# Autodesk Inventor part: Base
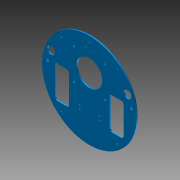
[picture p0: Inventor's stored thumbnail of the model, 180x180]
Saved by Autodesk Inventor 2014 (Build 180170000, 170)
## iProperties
Created: 2015-06
Part Number: Base
Material: Generic
Document SubType Name: Modeling
Designer: common
Density: 1 g/cm^3
Appearance: Default
Author: common
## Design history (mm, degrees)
node "Base.ipt1"
body "Solid2"
node "Base1"
